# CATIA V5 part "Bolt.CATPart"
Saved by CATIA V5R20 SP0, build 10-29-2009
Part number: Bolt
Bounding box of the stored display mesh (mm): x -8 to 40, y -12.478 to 12.478, z -11.18 to 11.18
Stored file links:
  C:\Users\Robin\Desktop\Delar\Bolt.CATPart
  C:\Program Files\Dassault Systemes\B20\win_b64\reffiles\standard\MetricThinPitch.txt
  C:\Program Files\Dassault Systemes\B20\win_b64\reffiles\standard\MetricThickPitch.txt
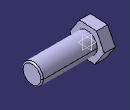
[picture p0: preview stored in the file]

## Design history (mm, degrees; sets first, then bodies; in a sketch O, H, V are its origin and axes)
Body1 (main body)
  Sketch1 on yz-plane, origin (0, 0, 0), H (0, 1, 0), V (0, 0, 1)
    circle A1 centre (0, 0) radius 7.5
    point P1 (0, 0)
    radius A1 = 7.5
    coincidence: P1 O
  Pad1: profile Sketch1, direction (1, 0, 0), length 40
  Fillet1: radius 1, on end face of Pad1
  Thread1: diameter 15, depth 40, pitch 1, on face of Pad1 from Sketch1.A1, from end face of Pad1
  Sketch2 on yz-plane, origin (0, 0, 0), H (0, 1, 0), V (0, 0, 1)
    point P1 (0, 0)
    point P2 (-12.4775, 0.7489)
    point P3 (-6.8874, -10.4314)
    point P4 (5.5902, -11.1803)
    point P5 (12.4775, -0.7489)
    point P6 (6.8874, 10.4314)
    point P7 (-5.5902, 11.1803)
    point P8 (-9.6825, -4.8412)
    line L1 (-12.4775, 0.7489) -> (-6.8874, -10.4314)
    line L2 (-6.8874, -10.4314) -> (5.5902, -11.1803)
    line L3 (5.5902, -11.1803) -> (12.4775, -0.7489)
    line L4 (12.4775, -0.7489) -> (6.8874, 10.4314)
    line L5 (6.8874, 10.4314) -> (-5.5902, 11.1803)
    line L6 (-5.5902, 11.1803) -> (-12.4775, 0.7489)
    construction line L7 (0, 0) -> (-9.6825, -4.8412)
    construction circle A1 centre (0, 0) radius 12.5
    construction arc A2 centre (6.8874, 10.4314) radius 12.5 from (12.4775, -0.7489) to (-5.5902, 11.1803) cw
    construction arc A3 centre (-6.8874, -10.4314) radius 12.5 from (5.5902, -11.1803) to (-12.4775, 0.7489) ccw
    radius A1 = 12.5
    coincidence: A1 P2, A1 P3, A1 P4, A1 P5, A1 P6, A1 P7, A2 P1, A3 P1, P1 O
    midpoint: P8 L1
    parallelism: L1 L4
  Pad2: profile Sketch2, direction (-1, 0, 0), length 8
